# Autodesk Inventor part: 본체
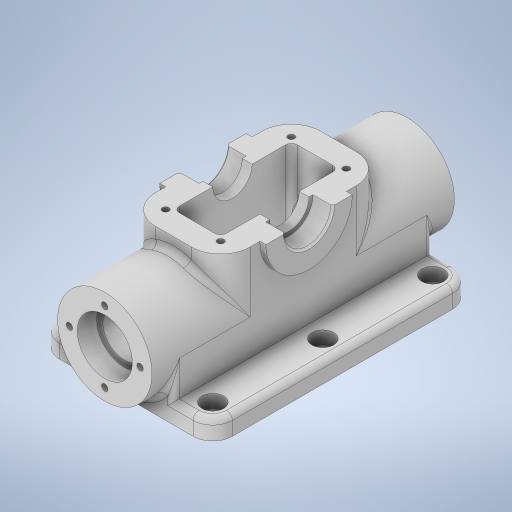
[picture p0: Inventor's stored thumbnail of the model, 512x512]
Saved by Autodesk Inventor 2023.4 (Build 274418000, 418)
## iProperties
Created: 2024-06
Part Number: 본체
Material: 일반
Document SubType Name: Modeling
Designer: edu-40
Density: 1 g/cm^3
Appearance: 기본값
Author: edu-40
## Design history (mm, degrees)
sketch "스케치1"
  geometry: L1 (27, -24)-(-27, -24); L2 (-42, -9)-(-42, 9); L3 (-27, 24)-(27, 24); L4 (42, 9)-(42, -9); A1 r 15 centre (27, -9) between (27, -24) and (42, -9); A2 r 15 centre (27, 9) between (42, 9) and (27, 24); A3 r 15 centre (-27, 9) between (-27, 24) and (-42, 9); A4 r 15 centre (-27, -9) between (-42, -9) and (-27, -24); 6 further points
  constraints: 8 end point, 8 point on circle, 8 tangent, 6 point on line, 4 centre point, 3 equal radius, 2 midpoint, 2 parallel, 1 horizontal, 1 horizontal alignment, 1 perpendicular, 1 vertical alignment
  dimensions: "d0" = 84 distance of point (42, -24) point (-42, -24); "d1" = 48 distance of point (42, 24) point (42, -24); "d2" = 15 radius of A1
extrude "돌출1" new body sketch "스케치1" distance "d3" = 59; taper "d4" = 0 deg
sketch "스케치2"
  geometry: L1 (56, -44)-(-56, -44); L2 (-66, -34)-(-66, 34); L3 (-56, 44)-(56, 44); L4 (66, 34)-(66, -34); A1 r 10 centre (56, -34) between (56, -44) and (66, -34); A2 r 10 centre (-56, -34) between (-66, -34) and (-56, -44); A3 r 10 centre (-56, 34) between (-56, 44) and (-66, 34); A4 r 10 centre (56, 34) between (66, 34) and (56, 44); 6 further points
  constraints: 8 end point, 8 point on circle, 8 tangent, 6 point on line, 4 centre point, 3 equal radius, 2 midpoint, 2 parallel, 1 horizontal, 1 horizontal alignment, 1 perpendicular, 1 vertical alignment
  dimensions: "d5" = 132 distance of point (66, -44) point (-66, -44); "d6" = 88 distance of point (66, 44) point (66, -44); "d7" = 10 radius of A1
extrude "돌출2" join sketch "스케치2" distance "d8" = 10; taper "d9" = 0 deg
sketch "스케치3"
  geometry: L1 (0, 34)-(0, -34) reference; L2 (10, -24)-(59, -24) reference; L3 (28, -24)-(10, -24); L4 (10, 24)-(59, 24) reference; L5 (28, 24)-(10, 24); L6 (10, -24)-(10, 24); L7 (10, 34)-(10, -34) reference; A1 r 24 centre (28, 0) between (28, -24) and (28, 24); 3 further points
  constraints: 6 end point, 3 collinear, 2 point on circle, 2 point on line, 1 centre point, 1 horizontal alignment
  dimensions: "d10" = 48 diameter of A1; "d11" = 28 distance from line of L1 A1.centre
extrude "돌출3" join sketch "스케치3" stored distance "d12" = 154; taper "d13" = 0 deg
extrude "돌출4" join sketch "스케치3" stored distance "d14" = 132; taper "d15" = 0 deg
sketch "스케치4"
  geometry: L1 (27, 59)-(-27, 59) reference; L2 (-22, 59)-(22, 59); A1 r 22 centre (0, 59) between (-22, 59) and (22, 59); 2 further points
  constraints: 2 end point, 2 midpoint, 2 point on circle, 2 point on line, 1 centre point, 1 vertical alignment
  dimensions: "d16" = 44 diameter of A1
extrude "돌출5" join sketch "스케치4" stored distance "d17" = 54; taper "d18" = 0 deg
sketch "스케치5"
  geometry: L1 (22, 59)-(-22, 59) reference; L2 (-12, 59)-(12, 59); A1 r 12 centre (0, 59) between (-12, 59) and (12, 59); 1 further point
  constraints: 2 end point, 2 point on circle, 2 point on line, 1 centre point, 1 midpoint
  dimensions: "d19" = 24 diameter of A1
extrude "돌출6" cut sketch "스케치5" distance "d20" = 10; taper "d21" = 0 deg
sketch "스케치6"
  geometry: L1 (22, 59)-(-22, 59) reference; L2 (-12, 59)-(12, 59); L3 (-56, 0)-(56, 0) reference; A1 r 12 centre (0, 59) between (-12, 59) and (12, 59); 3 further points
  constraints: 3 midpoint, 2 end point, 2 point on circle, 2 point on line, 1 centre point, 1 vertical alignment
  dimensions: "d22" = 24 diameter of A1
extrude "돌출7" cut sketch "스케치6" distance "d23" = 10; taper "d24" = 0 deg
sketch "스케치7"
  geometry: L1 (-12, 59)-(12, 59) reference; L2 (-10, 59)-(10, 59); L3 (-56, 0)-(56, 0) reference; A1 r 10 centre (0, 59) between (-10, 59) and (10, 59); 3 further points
  constraints: 3 midpoint, 2 end point, 2 point on circle, 2 point on line, 1 centre point, 1 vertical alignment
  dimensions: "d25" = 20 diameter of A1
extrude "돌출8" cut sketch "스케치7" extent not by distance; stored distance "d26" = 0; taper "d27" = 0 deg
sketch "스케치8"
  geometry: L1 (27, -12)-(-27, -12); L2 (-30, -9)-(-30, 9); L3 (-27, 12)-(27, 12); L4 (30, 9)-(30, -9); A1 r 3 centre (27, -9) between (27, -12) and (30, -9); A2 r 3 centre (27, 9) between (30, 9) and (27, 12); A3 r 3 centre (-27, 9) between (-27, 12) and (-30, 9); A4 r 3 centre (-27, -9) between (-30, -9) and (-27, -12); 6 further points
  constraints: 8 end point, 8 point on circle, 8 tangent, 6 point on line, 4 centre point, 3 equal radius, 2 midpoint, 2 parallel, 1 horizontal, 1 horizontal alignment, 1 perpendicular, 1 vertical alignment
  dimensions: "d28" = 60 distance of point (30, -12) point (-30, -12); "d29" = 24 distance of point (-30, -12) point (-30, 12); "d30" = 3 radius of A1 (derived)
extrude "돌출9" cut sketch "스케치8" extent not by distance; stored distance "d31" = 0; taper "d32" = 0 deg
sketch "스케치9"
  geometry: C1 r 14 at (0, 0); 1 further point
  constraints: 1 centre point
  dimensions: "d33" = 28 diameter of C1
extrude "돌출10" cut sketch "스케치9" distance "d34" = 10; taper "d35" = 0 deg
sketch "스케치10"
  geometry: C1 r 14 at (0, 0); 1 further point
  constraints: 1 centre point
  dimensions: "d36" = 28 diameter of C1
extrude "돌출11" cut sketch "스케치10" distance "d37" = 10; taper "d38" = 0 deg
sketch "스케치11"
  geometry: C1 r 11 at (0, 0); 1 further point
  constraints: 1 centre point
  dimensions: "d39" = 22 diameter of C1
extrude "돌출12" cut sketch "스케치11" extent not by distance; stored distance "d40" = 0; taper "d41" = 0 deg
chamfer "모따기1" distance "d42" = 1; stored, may be unused: second distance "d43" = 2, angle "d44" = 45 deg
chamfer "모따기2" distance "d45" = 1; stored, may be unused: second distance "d46" = 2, angle "d47" = 45 deg
fillet "모깎기1" dims "d48" = 3
sketch "스케치12"
  geometry: C1 r 24 at (0, 0) reference; A1 r 18 centre (0, 0) between (0, 18) and (18, 0); 3 further points
  constraints: 4 point on circle, 2 horizontal alignment, 2 vertical alignment, 1 centre point, 1 concentric
  dimensions: "d56" = 36 diameter of A1
hole "구멍1" sketch "스케치12" at (0, 18), (-18, 0), (18, 0), (0, -18) diameter "d49" = 3.242; stored, may be unused: countersink angle "d53" = 90 deg, drill point angle "d55" = 118 deg; dims "d50" = 8, "d51" = 4, "d52" = 2, "d54" = 10
sketch "스케치13"
  geometry: C1 r 24 at (0, 0) reference; A1 r 18 centre (0, 0) between (0, 18) and (18, 0); 3 further points
  constraints: 4 point on circle, 2 horizontal alignment, 2 vertical alignment, 1 centre point, 1 concentric
  dimensions: "d64" = 36 diameter of A1
hole "구멍2" sketch "스케치13" at (0, 18), (-18, 0), (18, 0), (0, -18) diameter "d57" = 3.242; stored, may be unused: countersink angle "d61" = 90 deg, drill point angle "d63" = 118 deg; dims "d58" = 8, "d59" = 4, "d60" = 2, "d62" = 10
sketch "스케치14"
  geometry: L1 (56, 44)-(-56, 44) reference; L2 (-66, 34)-(-66, 27) reference; 2 further points
  dimensions: "d72" = 10 distance from line of point (-56, 34) L1; "d73" = 10 distance from line of L2 point (-56, 34)
hole "구멍3" sketch "스케치14" at (-56, 34) diameter "d65" = 6.6; stored, may be unused: countersink angle "d69" = 90 deg, drill point angle "d71" = 0 deg; dims "d66" = 8, "d67" = 11, "d68" = 6.6, "d70" = 10
sketch "스케치15"
  geometry: L1 (-56, -44)-(56, -44) reference; L2 (-66, -21)-(-66, -34) reference; 6 further points
  constraints: 3 vertical alignment, 2 horizontal alignment
  dimensions: "d81" = 10 distance from line of L1 point (-56, -34); "d82" = 10 distance from line of L2 point (-56, -34); "d83" = 112 distance of point (56, -34) point (-56, -34)
hole "구멍4" sketch "스케치15" at (0, 33.726), (56, 33.946), (56, -34), (0, -34), (-56, -34) diameter "d74" = 6.6; stored, may be unused: countersink angle "d78" = 90 deg, drill point angle "d80" = 118 deg; dims "d75" = 6, "d76" = 11, "d77" = 6.6, "d79" = 8
sketch "스케치16"
  geometry: 5 further points
  constraints: 2 horizontal alignment, 2 vertical alignment
  dimensions: "d91" = 32 horizontal distance of point (0, 0) point (-32, 14); "d92" = 14 vertical distance of point (0, 0) point (32, 14); "d93" = 14 vertical distance of point (0, 0) point (-32, -14); "d94" = 32 horizontal distance of point (0, 0) point (32, -14)
hole "구멍5" sketch "스케치16" at (-32, 14), (-32, -14), (32, -14), (32, 14) diameter "d84" = 3.242; stored, may be unused: countersink angle "d88" = 90 deg, drill point angle "d90" = 118 deg; dims "d85" = 8, "d86" = 11, "d87" = 6.6, "d89" = 10
node "솔리드1"
feature "A9D066F2-1C7D-4E18-AEED-F7BC21143FA4" dims "d49" = 3.242, "d50" = 8, "d51" = 4, "d52" = 2, "d53" = 90 deg, "d54" = 10, "d55" = 118 deg
